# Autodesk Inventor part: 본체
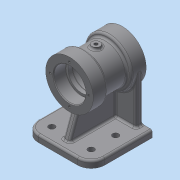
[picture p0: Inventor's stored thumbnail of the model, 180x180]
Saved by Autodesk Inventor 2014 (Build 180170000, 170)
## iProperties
Created: 2020-06
Part Number: 본체
Material: Generic
Document SubType Name: Modeling
Designer: kh
Density: 1 g/cm^3
Appearance: Default
Mass: 268.778 g
Surface Area: 642.091 cm^2
Volume: 268.778 cm^3
Author: kh
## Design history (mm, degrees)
sketch "Sketch1"
  geometry: L1 (-45, 49)-(45, 49); L2 (45, 49)-(45, -49); L3 (45, -49)-(-45, -49); L4 (-45, -49)-(-45, 49); L5 (-45, 49)-(45, -49); L6 (45, 49)-(-45, -49); 1 further point
  constraints: 12 end point, 2 midpoint, 2 parallel, 1 horizontal, 1 perpendicular
  dimensions: "d0" = 90 distance of L1.start L1.end; "d1" = 98 distance of L1.end L2.end
extrude "Extrusion1" new body sketch "Sketch1" distance "d2" = 10; taper "d3" = 0 deg
sketch "Sketch2"
  geometry: L1 (-50, 80)-(28, 80); L2 (-45, 0)-(45, 0) reference; L3 (-45, 0)-(-45, 10) reference; L4 (45, 10)-(-45, 10) reference; L5 (45, 0)-(45, 10) reference; L6 (-50, 80)-(-50, 115); L7 (-50, 115)-(-28, 115); L8 (-28, 115)-(-28, 109); L9 (-28, 109)-(6, 109); L10 (6, 109)-(6, 115); L11 (6, 115)-(28, 115); L12 (28, 115)-(28, 80); 1 further point
  constraints: 16 end point, 5 parallel, 1 collinear, 1 horizontal, 1 perpendicular
  dimensions: "d4" = 5 horizontal distance of L2.start L1.start; "d5" = 78 distance of L1.start L1.end; "d6" = 80 distance between parallel lines of L1 L2; "d7" = 22 distance of L6.end L7.end; "d8" = 22 distance of L10.end L11.end; "d9" = 70 diameter of L7 L1; "d10" = 70 diameter of L11 L1 (= d9); "d11" = 58 diameter of L9 L1
revolve "Revolution1" sketch "Sketch2" stored, may be unused: angle "d12" = 90 deg
sketch "Sketch3"
  geometry: L1 (45, -49)-(45, 49) reference; L2 (45, -35)-(35, -35); L3 (35, -35)-(35, 35); L4 (35, 35)-(45, 35); L5 (45, 35)-(45, -35); L6 (45, -35)-(35, 35); L7 (35, -35)-(45, 35); 4 further points
  constraints: 12 end point, 4 midpoint, 2 parallel, 1 collinear, 1 horizontal, 1 horizontal alignment, 1 perpendicular
  dimensions: "d13" = 70 distance of L2.end L3.end; "d14" = 10 distance of L2.start L2.end
extrude "Extrusion2" join sketch "Sketch3" stored distance "d15" = 10; taper "d16" = 0 deg
sketch "Sketch4"
  geometry: L1 (20.261, 45)-(33, 10); L2 (-28, 51)-(6, 51) reference; L3 (45, 10)-(-45, 10) reference; L4 (6, 45)-(28, 45) reference; L5 (20.261, 45)-(14.583, 60.6); L6 (14.583, 60.6)-(-38.145, 60.6); L7 (-38.145, 60.6)-(-38.145, 10); L8 (-38.145, 10)-(33, 10); 1 further point
  constraints: 10 end point, 3 point on line, 2 perpendicular, 1 collinear, 1 parallel
  dimensions: "d17" = 12 distance of L3.start L1.end; "d18" = 70 deg angle of L3 L1
extrude "Extrusion3" join sketch "Sketch4" stored distance "d19" = 10; taper "d20" = 0 deg
sketch "Sketch6"
  geometry: L1 (-50, 45)-(-50, 115) reference; L2 (28, 45)-(28, 115) reference; L3 (-50, 80)-(28, 80); L4 (-50, 80)-(-50, 103.5); L5 (-50, 103.5)-(-32, 103.5); L6 (-32, 103.5)-(-32, 100); L7 (-32, 100)-(-26, 100); L8 (-26, 100)-(-26, 103); L9 (-26, 103)-(4, 103); L10 (4, 103)-(4, 100); L11 (4, 100)-(10, 100); L12 (10, 100)-(10, 103.5); L13 (10, 103.5)-(28, 103.5); L14 (28, 103.5)-(28, 80); 3 further points
  constraints: 24 end point, 6 parallel, 4 midpoint, 3 collinear, 3 perpendicular, 2 point on line, 1 vertical alignment
  dimensions: "d21" = 47 diameter of L5 L3; "d22" = 40 diameter of L7 L3; "d23" = 46 diameter of L9 L3; "d24" = 18 distance of L4.end L5.end; "d25" = 18 distance of L12.end L13.end; "d26" = 6 distance of L6.end L7.end; "d84" = 30 distance of L8.end L9.end (derived); "d85" = 6 distance of L10.end L11.end (derived)
revolve "Revolution2" sketch "Sketch6" stored, may be unused: angle "d28" = 90 deg
workplane "Work Plane2"
sketch "Sketch8"
  geometry: L1 (50, 35)-(50, -35) reference; C1 r 6 at (11, 0); 2 further points
  constraints: 1 centre point, 1 horizontal alignment, 1 midpoint
  dimensions: "d35" = 39 distance from line of L1 C1.centre; "d36" = 12 diameter of C1
extrude "Extrusion5" join sketch "Sketch8" stored distance "d37" = 3; taper "d38" = 0 deg
sketch "Sketch9"
  geometry: C1 r 23.5 at (0, 0) reference; 2 further points
  constraints: 1 horizontal alignment
  dimensions: "d39" = 28.5 distance of point (28.5, 0) C1.centre
hole "Hole1" sketch "Sketch9" at (28.5, 0) diameter "d40" = 3.242; stored, may be unused: countersink angle "d44" = 90 deg, drill point angle "d46" = 118 deg; dims "d41" = 10, "d42" = 4, "d43" = 2, "d45" = 12
pattern_circular "Circular Pattern1" dims angle "d48" = 360 deg
workplane "Work Plane3"
mirror "Mirror1"
hole "Hole2" diameter "d52" = 4.917; stored, may be unused: countersink angle "d56" = 90 deg, drill point angle "d58" = 118 deg; dims "d50" = 10, "d51" = 10, "d53" = 10, "d54" = 4, "d55" = 2, "d57" = 17.5
fillet "Fillet1" dims "d59" = 20
hole "Hole3" diameter "d64" = 9; stored, may be unused: countersink angle "d68" = 90 deg, drill point angle "d70" = 0 deg; dims "d62" = 10, "d63" = 10, "d65" = 10, "d66" = 4, "d67" = 2, "d69" = 17.5
pattern_linear "Rectangular Pattern1" dims "d73" = 36
sketch "Sketch11"
  geometry: L1 (0, 10)-(0, 0) reference; L2 (-70, 10)-(0, 10) reference; 2 further points
  constraints: 1 other
  dimensions: "d76" = 45 distance from line of L1 point (-45, 6); "d77" = 4 distance from line of L2 point (-45, 6)
emboss "Emboss1" sketch "Sketch11" dims "d0" = 90, "d1" = 98, "d11" = 58, "d79" = 0.5, "d80" = 0
fillet "Fillet2" dims "d78" = 3
fillet "Fillet3" dims "d81" = 3
fillet "Fillet4" dims "d82" = 0.3, "d92" = 3
chamfer "Chamfer1" distance "d86" = 1; stored, may be unused: second distance "d87" = 2, angle "d88" = 45 deg
chamfer "Chamfer2" distance "d89" = 1; stored, may be unused: second distance "d90" = 2, angle "d91" = 45 deg
body "Solid1"
node "Projected Loop1"
other parameters: "d34" = 102
